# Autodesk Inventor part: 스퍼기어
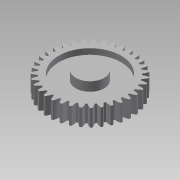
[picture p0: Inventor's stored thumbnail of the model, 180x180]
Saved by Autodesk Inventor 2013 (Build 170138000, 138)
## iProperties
Created: 2013-08
Part Number: 스퍼기어
Material: 강
Document SubType Name: Modeling
Designer: 한국산업디자인학원
Categories: <?xml version="1.0" encoding="UTF-16"?> <MemberInstance><Categories><FamilyTemplate><FamilyTemplateParameter ValueType="xs:double" Id="1" ObjectReferenceKey="da
Density: 1 g/cm^3
CustomPartVersion: 1
Author: 한국산업디자인학원
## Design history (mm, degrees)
sketch "Sketch1"
  geometry: C1 r 37 at (0, 0)
  constraints: 1 centre point
  dimensions: "d0" = 74 diameter of C1 (= da_da)
extrude "Extrusion1" new body sketch "Sketch1" distance "d1" = 15 (= da_b); taper "d2" = 0 deg
workplane "Work Plane2"
feature "피치 지름" dims "d4" = 10, "d5" = 0
workplane "Work Plane8"
workplane "Work Plane9"
feature "스퍼 기어" dims "da_b" = 15, "da_d" = 70, "da_aw" = 70, "da_da" = 74, "da_df" = 65, "da_dw" = 70, angle "da_beta" = 0 deg, "da_lefttooth" = 0, "da_righttooth" = 0
sketch "스케치3"
  geometry: L1 (0.729, 15)-(-0.729, 15) reference; L2 (0, 0)-(0, 15); L3 (-12.5, 0)-(-12.5, 5); L4 (-12.5, 5)-(-27.5, 5); L5 (-27.5, 5)-(-27.5, 0); L6 (-27.5, 0)-(-12.5, 0); L7 (-27.5, 10)-(-12.5, 10); L8 (-12.5, 10)-(-12.5, 15); L9 (-12.5, 15)-(-27.5, 15); L10 (-27.5, 10)-(-27.5, 15)
  constraints: 18 end point, 5 parallel, 3 perpendicular, 2 equal length, 2 horizontal alignment, 1 collinear, 1 midpoint
  dimensions: "d49" = 5 distance between parallel lines of L4 L6; "d51" = 55 diameter of L5 L2; "d52" = 25 diameter of L3 L2
revolve "회전1" sketch "스케치3" stored, may be unused: angle "d53" = 90 deg
sketch "스케치4"
  geometry: C1 r 12.5 at (0, 0) reference; C2 r 12.5 at (0, 0)
  constraints: 1 centre point, 1 coincident, 1 concentric
extrude "돌출2" join sketch "스케치4" distance "d54" = 3; taper "d55" = 0 deg
sketch "스케치5"
  geometry: C1 r 12.5 at (0, 0) reference; C2 r 12.5 at (0, 0)
  constraints: 1 centre point, 1 coincident, 1 concentric
extrude "돌출3" join sketch "스케치5" distance "d56" = 13; taper "d57" = 0 deg
body "Solid1"
sketch "Sketch2"
  geometry: C1 r 37 at (0, 0) reference; C2 r 35 at (0, 0)
  constraints: 1 centre point, 1 coincident
  dimensions: "d3" = 70 diameter of C2 (= da_dw)
body "Srf1"
other parameters: "d17" = 0, "d34" = 0.8976 (computed from da_z), "d39" = 0, "d41" = 0, "d47" = 0, "d48" = 0
